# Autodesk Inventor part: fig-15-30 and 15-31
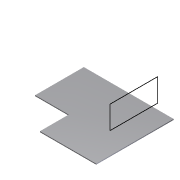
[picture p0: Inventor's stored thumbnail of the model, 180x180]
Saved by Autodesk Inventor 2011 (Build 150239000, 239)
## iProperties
Created: 2005-03
Part Number: fig-15-30 and 15-31
Document SubType Name: Sheet Metal
Designer: CADCIM
Manufacturer: Standard
Standards Organization: Custom
Density: 1 g/cm^3
Sheet Metal Rule: Default
Author: CADCIM
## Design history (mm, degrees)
node "Face1"
  sketch "Sketch1" dims "JacobiRadiusSize" = 0.5 (= Thickness)
    geometry: L1 (29.25, 32.25)-(-19.875, 32.25); L2 (-19.875, 32.25)-(-19.875, 5.625); L3 (-19.875, 5.625)-(-1.5, 5.625); L4 (-1.5, 5.625)-(-1.5, -10.125); L5 (-1.5, -10.125)-(29.25, -10.125); L6 (29.25, -10.125)-(29.25, 32.25)
    constraints: 12 end point, 4 parallel, 1 horizontal, 1 perpendicular
sketch "Sketch2"
  geometry: L1 (-12.475, 7.526)-(-25.013, 7.526); L2 (-25.013, 7.526)-(-25.013, 33.56); L3 (-25.013, 33.56)-(-12.475, 33.56); L4 (-12.475, 33.56)-(-12.475, 7.526)
  constraints: 8 end point, 2 parallel, 1 horizontal, 1 perpendicular
body "Solid1"
face "Plate1" dims "Thickness" = 0.5
other parameters: "BendRadius" = 0.5 (= Thickness), "BendReliefWidth" = 0.5 (= Thickness), "BendReliefDepth" = 0.25 (= 0.5 x Thickness), "CornerReliefSize" = 2 (= 4 x Thickness), "SeamGap" = 0.01, "MinimumRemnant" = 1 (= 2 x Thickness), "TransitionRadius" = 0.5 (= BendRadius), "d0" = 0.5 (= BendRadius), "GapSize" = 0.5 (= Thickness)
